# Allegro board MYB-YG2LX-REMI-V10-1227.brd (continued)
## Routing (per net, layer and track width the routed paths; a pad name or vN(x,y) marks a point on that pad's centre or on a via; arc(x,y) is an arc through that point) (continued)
VDD_3V3: length 106.5
  TOP w0.254: U15.3 35.21,21.28 v1(34.97,21.51) 35.19,21.73 U15.2 ; U10.28 98.86,52.06 v1(99.39,51.54) ; U10.21 93.8,53.01 v1(93.58,53.23) ; U7.19 v1(24.19,36.67) ; v1(95.07,57.68) 95.4,57.35 U10.14
  TOP w0.381: v1(13.05,27.3) 13.08,27.3 13.62,27.84 R83.1 ; R85.1 v1(14.17,34.36) ; R11.1 C19.1 v1(32.74,47.37) ; R175.2 96.95,43.21 96.57,43.59 v1(95.88,43.59) ; R175.2 R174.2 ; R175.2 v1(96.3,42.88) ; U24.16 40.21,53.51 40.21,53.51 40.75,53.51 v1(41.19,53.95) ; R138.2 R137.2 v1(98.09,23.8) ; v1(31.01,50.16) 31.01,50.25 R241.2 ; R84.1 v1(14.2,30.5) ; 30.73,32.08 30.73,37.57 30.15,38.15 v1(27.94,38.15) 27.77,37.98 R32.1 ; R33.1 v1(27.89,35.12)
  ART03 w0.381: v1(74.01,13.79) 74.34,13.79 75.26,14.71 v1(75.74,14.71)
  ART04 w0.381: v1(24.19,36.67) 25.67,38.15 v1(27.94,38.15) ; v1(27.89,35.12) 27.89,34.06 v1(29.38,32.56) ; v1(84.15,67.45) 84.15,65 84.79,64.36 v1(84.79,55.26)
  BOTTOM w0.203: C39.1 47.6,19.48 U8.7
  BOTTOM w0.254: v1(22.58,5.38) 22.2,5.01 U14.3 20.36,5.01 20.18,5.19 20.18,6.3 20.51,6.63 C90.1 ; v1(19.4,5.01) U14.6 17.9,5.01 17.5,5.41 R108.1 ; v1(41.77,48.73) 40.62,48.73 40.4,48.96 U23.16
  BOTTOM w0.305: v1(83.21,15.44) 82.75,15.44 R43.1
  BOTTOM w0.381: C33.1 C34.1 25.2,35.65 v1(24.19,36.67) ; R193.2 91.44,38.89 90.55,38.89 89.99,38.33 v1(89.99,38.07) 89.99,37.74 v1(89.73,37.49) ; v1(8.61,21.59) 8.49,21.59 8.11,21.97 Q6.1 ; Q7.1 v1(8.79,28.45) ; R249.1 v1(84.15,67.45) ; C39.1 47.27,17.99 C40.1 v1(46.26,17.64) ; R250.1 v1(105.15,3.87) ; R46.1 R44.1 73.78,13.56 v1(74.01,13.79) ; v1(98.14,11.43) 97.25,11.43 96.66,12.03 R164.1 ; v1(99.39,51.54) 98.84,52.08 C62.1 ; R201.1 v1(99.6,29.91) ; v1(31.01,50.16) 31.01,50.37 31.75,51.11 R241.2 ; R257.1 8.3,26.55 v1(8.51,26.75) ; v1(95.07,57.68) 96.02,56.73 C60.1 ; R267.1 9.91,31.78 v1(9.8,31.67) ; v1(92.2,21.74) 91.81,21.36 R156.2 ; v1(114.98,6.65) 115.23,6.4 R247.1 ; v1(8.66,35) 8.75,35.09 Q9.1 ; v1(96.36,29.95) 96.36,30.82 R199.1 R200.1 ; C63.1 v1(93.58,53.23) ; Q8.1 9.29,32.17 v1(9.29,32.36) ; R115.1 35.71,22.25 v1(34.97,21.51) ; R254.1 v1(41.97,47.52) ; v1(102.97,3) R57.2 ; R261.1 8.18,19.41 v1(8.53,19.76) ; R54.1 v1(93.52,54.13) ; R263.1 v1(9.9,34.83) ; C61.1 v1(100.02,56.54) ; R107.1 v1(22.58,5.38) ; R39.1 v1(84.79,55.26) ; v1(92.76,10.77) 93.37,10.77 93.73,11.14 R162.1 R163.1
  vias: v1(10.46,60.15) v1(10.46,59.74) v1(10.46,59.33) v1(10.87,60.15) v1(10.87,59.74) v1(10.87,59.33) v1(24.68,48.11) v1(24.66,47.62) v1(25.14,48.08) v1(25.09,47.62) v1(25.55,47.68) v1(25.95,47.75) v1(29.38,32.13) v1(29.82,32.56) v1(29.82,32.13) v1(31.8,18.11) v1(31.82,17.68) v1(32.23,18.08) v1(32.25,17.65) v1(39.32,63.47) v1(39.32,63.04) v1(39.32,62.64) v1(39.32,62.2) v1(39.32,61.8) v1(39.39,37.94) v1(39.39,37.51) v1(39.39,37.05) v1(39.72,63.47) v1(39.82,37.94) v1(39.82,37.51) v1(39.82,37.05) v1(40.26,37.94) v1(40.26,37.51) v1(40.26,37.05) v1(47.14,15.52) v1(47.16,15.98) v1(47.6,15.95) v1(47.57,15.49) v1(54.56,15.44) v1(54.96,15.44) v1(59.18,61.9) v1(59.18,61.49) v1(59.58,61.9) v1(59.58,61.49) v1(71.45,62.94) v1(71.45,62.53) v1(71.45,62.13) v1(71.45,61.72) v1(89.38,13.31) v1(89.38,12.9) v1(89.84,13.28) v1(89.84,12.87) v1(99.5,28.53) v1(99.5,27.87) v1(100.63,10.59) v1(101.16,10.62) v1(101.49,24.59) v1(101.6,30.22) v1(102.13,30.22) v1(102.18,24.59)
VDD_5V: length 24.1
  TOP w0.381: R10.1 31.99,44.52 v1(32.3,44.83) ; v1(42.9,27.86) 42.62,28.14 R16.1
  ART03 w0.381: v1(39.52,34.29) 39.52,32.64 40.03,32.13 40.94,32.13 42.9,30.18 v1(42.9,27.86)
  BOTTOM w0.254: v1(79.96,10.36) 80.69,10.36 80.94,10.62 U9.24 ; U14.7 19.3,5.51 19.61,5.82 C91.1
  BOTTOM w0.381: C42.1 76.65,12.09 R38.1 ; D26.1 v1(16.4,14.45) ; R110.1 v1(23.63,7.15) ; v1(17.09,7.24) 16.58,7.24 16.19,6.85 R109.1 ; D25.1 v1(13,13.97) ; C91.1 19.61,7.51 v1(19.1,8.03)
  vias: v1(11.1,41.1) v1(11.1,40.59) v1(11.6,41.1) v1(11.6,40.59) v1(12.11,41.1) v1(12.11,40.59) v1(13.43,18.14) v1(13.43,17.37) v1(14.19,18.14) v1(14.19,17.37) v1(14.96,18.14) v1(14.96,17.37) v1(16.17,60.3) v1(16.17,59.87) v1(16.17,59.41) v1(16.61,60.3) v1(16.61,59.87) v1(16.61,59.41) v1(17.04,60.3) v1(17.04,59.87) v1(17.04,59.41) v1(17.47,60.3) v1(17.47,59.87) v1(17.47,59.41) v1(30.14,39.83) v1(30.14,39.4) v1(30.14,38.94) v1(30.19,10.64) v1(30.19,10.21) v1(30.19,9.78) v1(30.45,16.69) v1(30.45,16.26) v1(30.45,15.8) v1(30.58,39.83) v1(30.58,39.4) v1(30.58,38.94) v1(30.63,10.64) v1(30.63,10.21) v1(30.63,9.78) v1(30.88,16.69) v1(30.88,16.26) v1(30.88,15.8) v1(31.01,39.83) v1(31.01,39.4) v1(31.01,38.94) v1(31.06,10.64) v1(31.06,10.21) v1(31.06,9.78) v1(31.31,16.69) v1(31.31,16.26) v1(31.31,15.8) v1(31.49,10.64) v1(31.49,10.21) v1(31.49,9.78) v1(31.74,16.69) v1(31.74,16.26) v1(31.74,15.8) v1(40.92,66.55) v1(40.92,66.14) v1(41.32,66.55) v1(41.32,66.14) v1(41.73,66.55) v1(41.73,66.14) v1(76.32,9.32) v1(76.32,8.86) v1(76.88,9.32) v1(76.88,8.86) v1(93.95,2.9) v1(94.36,2.9) v1(94.76,2.9) v1(95.17,2.87) v1(95.44,48.41) v1(95.44,47.9) v1(95.94,48.41) v1(95.94,47.9) v1(100.87,47.7) v1(100.87,47.19) v1(100.87,46.69) v1(101.38,47.7) v1(101.38,47.19) v1(101.38,46.69)
VDD_5V_VBUS: length 1.3
  BOTTOM w0.381: v1(94.61,51.54) 95.14,51.54 R55.1
  vias: v1(106.17,50.16) v1(106.17,49.66) v1(106.17,49.15) v1(106.68,50.16) v1(106.68,49.66) v1(106.68,49.15)
VDD_ADC_VREF: length 3.4
  TOP w0.254: v1(41.78,20.85) 41.49,20.85 C107.1 41,21.28 U15.19
  BOTTOM w0.254: v1(41.78,20.85) 41.4,21.23 R130.2
VDD_BAT: length 30.6
  ART04 w0.381: v1(69.82,63.86) v1(70.23,63.86) v1(70.63,63.86) 71.93,63.86 72.44,63.35 78.2,63.35 83.1,68.25 86.66,68.25 88.95,65.96 88.95,60.52 J14.1
VDD_BL_3V3: length 44.8
  TOP w0.254: R236.2 v1(25.23,41.36) ; v1(27.9,41.31) 28.28,41.69 R211.2 ; R235.2 v1(23.45,41.31) ; v1(19.3,41.35) 19.3,41.7 R238.2 ; R239.2 v1(19.9,41.38) ; R237.2 v1(16.34,41.31) ; R240.2 v1(21.68,41.31) ; R215.2 v1(27.01,41.31)
  TOP w0.381: v1(27.81,46.35) 28.16,46 29.94,46 30.43,46.49 v1(31.24,46.49) ; v1(27.81,46.35) v1(27.81,47.32) ; v1(27.81,46.35) 26.08,46.35 25.69,45.96 U22.34 25.69,44.82 v1(26.11,44.4) ; v1(27.81,46.35) 27.49,46.03 U22.36 v1(27.49,44.27)
  TOP w0.508: R214.2 32.06,59.78 31.57,60.27 29.38,60.27 27.02,57.91 27.02,53.34 v1(27.89,52.48)
  ART03 w0.381: v1(16.34,41.31) 16.34,46.01 17.85,47.52 19.47,47.52 19.85,47.14 v1(20.24,47.14)
  BOTTOM w0.381: v1(16.34,41.31) 17.07,42.04 18.92,42.04 19.3,41.66 v1(19.3,41.35) ; R229.1 21.15,47.14 v1(20.24,47.14) ; R213.2 v1(31.24,46.49) ; v1(27.89,52.48) 27.89,52.62 28.27,53 R212.2
VDD_LDO: length 9.8
  TOP w0.102: 68.85,10.53 68.85,11.85 ; 69.85,10.53 69.85,11.85 ; 67.85,10.53 67.85,11.85 ; 70.85,10.53 70.85,11.85
  TOP w0.203: 67.79,10.31 67.41,9.93 v1(67.41,9.46)
  BOTTOM w0.152: v1(67.41,9.46) 67.06,9.12 66.44,9.12 66.23,9.33 U2.7
  BOTTOM w0.381: R3.2 v1(71.07,12.81) 71.13,12.75 C13.1
VDD_PHY0_3V3: length 2.1
  TOP w0.152: 90.32,17.68 90.44,17.56 U16.31
  TOP w0.254: R155.1 v1(100.05,23.8)
  vias: v1(90.52,17.91) v1(90.93,17.91) v1(101.52,21.46) v1(102.51,21.49)
VDD_PHY1_3V3: length 25.9
  TOP w0.152: U19.31 90.41,37.19 90.32,37.29
  TOP w0.254: v1(99.31,43.71) 99.61,43.41 R191.1
  ART04 w0.508: 92.45,37.77 92.45,38.76 93.26,39.57 96.11,39.57 97.25,40.72 98.14,40.72 98.65,41.22 98.65,42.42 99.31,43.08 v1(99.31,43.71) ; 92.45,37.36 92.45,32.34 v1(93.03,31.77) 93.14,31.66 93.59,31.66 v1(96.26,28.98) v1(96.92,28.98)
  BOTTOM w0.254: v1(93.03,31.77) C133.1 C134.1
  vias: v1(90.5,37.54) v1(90.9,37.54)
VDD_RGMII0: length 4.7
  TOP w0.254: v1(90.39,19.1) 91.14,18.36 U16.29
  TOP w0.305: v1(89.85,19.11) 89.86,19.1 v1(90.39,19.1)
  BOTTOM w0.254: R159.1 v1(86.65,28.41) ; R161.1 86.27,26.25 v1(86.65,26.63) R160.1
VDD_RGMII1: length 7
  TOP w0.203: U19.29 90.93,37.99 90.72,38.2 v1(90.72,38.23)
  BOTTOM w0.254: C148.1 R193.1 ; R198.1 84.18,44.51 v1(84.1,44.42)
  BOTTOM w0.305: v1(84.2,49.33) 85.28,50.4 R196.1 ; R197.1 84.18,41.99 v1(84.07,41.88)
  vias: v1(90.62,34.37) v1(90.62,33.81)
VDD_RTC: length 0.8
  BOTTOM w0.381: R256.1 v1(72,69.02)
  vias: v1(67.94,65) v1(67.94,64.59) v1(68.35,65) v1(68.35,64.59) v1(73.91,65.61) v1(73.91,65.2) v1(74.32,65.61) v1(74.32,65.2)
VDD_SD: length 31.8
  BOTTOM w0.381: R70.1 19.38,53.4 19.1,53.68 ; v1(15.44,51.13) 15.44,51.32 15.67,51.56 R72.1 ; 19.1,53.68 18.72,53.3 R71.1 ; 19.1,53.68 v1(19.1,54.13) ; R74.1 8.76,53.32 v1(8.35,52.91) ; R69.1 32.26,55.07 33.07,55.88 33.07,57.03 32.73,57.36 R68.1 31.71,59.22 31.29,59.64 21.32,59.64 v1(19.35,57.66) 19.25,57.56 J5.4 ; R73.1 12.91,51.44 v1(12.57,51.1)
  vias: v1(7.79,60.96) v1(7.79,60.55) v1(7.79,60.15) v1(8.2,60.96) v1(8.2,60.55) v1(8.2,60.15)
VDD_SOM_3V3OUT: length 228.9
  TOP w0.381: U26.87 v1(44.3,50.18)
  ART03 w0.508: v1(90.57,3.23) 90.9,3.56 99.95,3.56 100.19,3.8 v1(103,3.8) ; v1(58.7,8.33) 57.65,8.33 56.36,7.04 36.11,7.04 31.26,11.89 25.55,11.89 24.02,10.36 16.35,10.36 14.27,12.45 8.99,12.45 7.9,13.54 7.9,36.68 9.72,38.51 9.72,56.97 9.42,57.28 9.42,61.04
  ART04 w0.381: v1(44.3,50.18) 45.07,50.95 45.07,55.84 49.12,59.89 49.12,63.83 50.12,64.83 50.12,66.11 48.54,67.69 40.08,67.69 38.86,68.91 16.26,68.91 15.58,68.22 14.14,68.22 12.98,67.06 12.98,64.97 11.96,63.96 11.96,63.02 10.66,61.72 v1(10.64,61.72)
  ART04 w0.508: v1(90.57,3.23) 90.57,5.82 87.42,8.97 84.1,8.97 82.5,7.37 79.78,7.37 77.01,10.13 70.51,10.13 69.9,9.53 69.9,8.84 68.4,7.34 63.34,7.34 61.82,8.86 59.91,8.86 59.38,8.33 v1(58.7,8.33)
  BOTTOM w0.381: C173.1 46.67,50.18 U26.87 v1(44.3,50.18) ; R56.2 102.62,7.44 103,7.06 v1(103,3.8) R253.1
  vias: v1(10.64,61.32) v1(10.64,60.91)
VDD_SOM_5VIN:
  vias: v1(43.73,53.19) v1(43.73,51.19) v1(44.14,53.19) v1(44.14,51.19) v1(44.55,53.19) v1(44.55,51.19) v1(46.25,53.14) v1(46.25,51.21) v1(46.66,53.14) v1(46.66,51.21) v1(47.06,53.14) v1(47.06,51.21)
VDD_USB0_VBUS:
  vias: v1(78.51,4.5) v1(78.51,3.99) v1(78.51,3.48) v1(81.25,3.48) v1(81.76,4.5) v1(81.76,3.99) v1(81.76,3.48) v1(86.84,8.13) v1(86.84,7.62) v1(86.84,7.11) v1(87.35,8.13) v1(87.35,7.62) v1(87.35,7.11)
VDD_VBUS: length 0.2
  TOP w0.254: 63.33,7.15 J1.A4
  vias: v1(58.29,5.94) v1(58.29,5.51) v1(58.29,5.05) v1(58.72,5.94) v1(58.72,5.51) v1(58.72,5.05) v1(59.15,5.94) v1(59.15,5.51) v1(59.15,5.05) v1(59.58,5.94) v1(59.58,5.51) v1(59.58,5.05) v1(63.22,8.76) v1(63.22,8.33) v1(63.65,8.76) v1(63.65,8.33) v1(64.16,6.3) v1(67.71,6.38) v1(68.04,8.76) v1(68.04,8.33) v1(68.27,9.88) v1(68.27,9.45) v1(68.47,8.76) v1(68.47,8.33) v1(68.7,9.88) v1(68.7,9.45)
VDD_VBUS_5V: length 29.9
  ART04 w0.508: 33.65,18.97 33.65,14.5 35.18,12.98 37.94,12.98 44.37,6.55 52.45,6.55 54.81,4.19
  vias: v1(55.21,4.01) v1(55.21,3.56) v1(55.65,4.01) v1(55.65,3.56) v1(56.08,4.01) v1(56.08,3.56) v1(56.51,4.01) v1(56.51,3.56) v1(56.97,3.99) v1(56.97,3.53) v1(57.4,3.99) v1(57.4,3.53)
VDDA_AUDIO_3V3: length 3.7
  TOP w0.254: U15.17 39.84,20.38 39.98,20.24 39.98,19.85 ; U15.16 39.9,19.93 39.98,19.85 ; 39.98,19.85 40.23,19.6 v1(40.23,19.23)
  BOTTOM w0.381: 39.57,18.03 39.57,18.57 v1(40.23,19.23)
VDDA_PHY0_1V1: length 16.9
  TOP w0.203: v1(98.48,16.56) 98.28,16.76 U16.4 ; U16.9 98.56,18.76 v1(98.65,18.85)
  TOP w0.254: U16.47 96.56,14.33 97,13.89 v1(97.02,13.89)
  ART04 w0.508: 98.73,22.48 97.25,21.01 97.25,20.24 v1(98.65,18.85) 98.65,16.76 98.5,16.61 98.5,16.59 v1(98.48,16.56) 98.47,16.56 98.44,16.56 97.02,15.14 v1(97.02,13.89)
  BOTTOM w0.254: U16.9 98.56,18.76 v1(98.65,18.85) ; v1(98.62,24.48) FB11.2 97.5,24.48 ; C127.1 96.88,14.04 v1(97.02,13.89) ; v1(98.48,16.56) 98.28,16.76 U16.4
  vias: v1(99.03,24.49)
VDDA_PHY0_3V3: length 15.4
  TOP w0.254: v1(97.99,20.62) 97.76,20.4 U16.12 ; U16.1 97.76,14.48 98.42,13.82 v1(98.52,13.82)
  ART04 w0.508: v1(101.09,13.54) 101.06,13.51 v1(100.55,13.51) 99.69,14.38 ; v1(97.99,20.62) 98.78,20.62 99.69,19.71 99.69,14.38 ; 99.69,14.38 99.69,14.33 99.18,13.82 v1(98.52,13.82)
  BOTTOM w0.254: U16.12 97.76,20.4 v1(97.99,20.62) ; v1(98.52,13.82) 99.47,13.82 C120.1
VDDA_PHY1_1V1: length 16.8
  TOP w0.203: v1(98.48,36.2) 98.28,36.39 U19.4
  TOP w0.254: U19.47 96.56,33.99 97.55,32.99 v1(97.81,32.99) ; U19.9 98.56,38.39 v1(98.65,38.48)
  ART04 w0.508: v1(97.81,32.99) 97.81,35.54 v1(98.48,36.2) 98.65,36.37 v1(98.65,38.48) 99.49,39.32 v1(99.49,41.33) 99.95,41.33 v1(99.97,41.3)
  BOTTOM w0.254: C143.1 98.03,35.76 v1(98.48,36.2) ; C144.1 97.76,37.97 98.27,38.48 v1(98.65,38.48) ; v1(97.81,32.99) 97.4,32.99 96.88,33.52 C145.1
VDDA_PHY1_3V3: length 21.6
  TOP w0.254: v1(97.79,40.06) 97.76,40.03 U19.12 ; v1(98.62,33.73) 97.76,34.6 U19.1
  ART04 w0.508: v1(97.79,40.06) 97.79,37.06 96.74,36.02 96.74,32.59 97.46,31.88 100.45,31.88 101.09,32.51 v1(101.09,33.12) ; v1(101.09,33.12) 100.07,34.14 99.03,34.14 v1(98.62,33.73) ; v1(101.09,33.12) v1(101.62,33.12)
  BOTTOM w0.254: C135.1 97.76,40.03 v1(97.79,40.06) ; v1(98.62,33.73) 97.8,34.56 C136.1
VDDL_PHY0_1V1: length 38
  TOP w0.254: v1(92.73,24.63) 92.73,23.37 93.11,22.99 C124.1 U16.22
  ART04 w0.381: 88.41,14.71 88.41,18.26 87.96,18.72 85.67,18.72 84.2,20.19 84.2,29.08 85.06,29.95 86.71,29.95 87.17,29.49 91.21,29.49 92.17,28.52 92.17,27.1 92.71,26.57 93.67,26.57 ; 88.41,14.71 v1(87.63,14.71) ; 88.41,14.71 88.41,13.13 87.96,12.67 v1(87.63,12.67)
  BOTTOM w0.254: 96.2,24.48 v1(96.2,25.32)
  vias: v1(96.21,25.73)
VDDL_PHY1_1V1: length 1
  TOP w0.254: U19.22 v1(93.36,41.35)
  vias: v1(84.78,40.89) v1(85.21,41.35) v1(85.21,40.89) v1(100.1,44.22) v1(100.55,44.22)
32.7K_CLK: length 4.4
  TOP w0.152: U22.31 v1(22.99,46.17)
  BOTTOM w0.152: R232.2 23.94,47.9 C158.1 R233.1 24.05,46.74 23.49,46.17 v1(22.99,46.17)
AUD_MIC: length 32.8
  TOP w0.203: J8.5 44.61,2.2 44.92,2.51 D29.2 44.92,4.14 C105.1 R131.1 39.8,10.15 39.8,11.61 40.31,12.12 42.06,12.12 43.56,13.61 43.56,18.39 43.68,18.52 43.68,19.13 43.25,19.56 v1(41.93,19.56)
  BOTTOM w0.203: v1(41.93,19.56) 40.52,20.97 R130.1 40.52,24.32 R129.1
AUDIO1_LOUT_L: length 10.1
  TOP w0.381: J8.3 34.14,9.2 35.89,10.95 v1(35.89,12.37) ; v1(37.61,12.37) 37.63,12.38 D27.2 R124.1 39.35,13.04 C97.1 39.55,13.03 40.25,13.74 R116.2
  BOTTOM w0.381: v1(35.89,12.37) v1(37.61,12.37)
AUDIO1_LOUT_R: length 14.1
  TOP w0.381: R123.2 35.61,13.03 C98.1 35.9,13.04 D28.2 36.74,10.83 36.01,10.11 36.01,7.26 37.78,5.5 J8.6
AUDIO_AGND: length 41.5
  TOP w0.254: C108.2 42.5,22.61 v1(43.28,22.61) ; v1(43.23,21.31) C107.2 42.48,20.77 42.08,20.37 40.94,20.37 40.48,20.83 U15.18 ; R127.2 v1(42.96,17.98)
  TOP w0.381: D27.1 v1(37.63,14.61) ; D28.1 v1(36.74,14.61) ; C97.2 v1(39.36,14.6) ; C98.2 v1(35.89,14.6) ; R124.2 v1(38.52,14.61)
  TOP w0.508: J8.2 34.28,2.2 36.22,4.14 41.42,4.14 42.26,3.31 D29.1 44.04,4.14 C105.2 R131.2 39.19,9.88 39.19,11.73 v1(40.19,12.74) v1(40.95,12.74) v1(41.72,12.74)
  BOTTOM w0.152: 41.55,14.38 41.78,14.38
  BOTTOM w0.508: C106.2 38.71,19.35 39.19,19.84 40.61,19.84 41.68,18.77 42.59,18.77
AUDIO_MCLK: length 3.2
  TOP w0.152: U15.1 35.68,24.38 C94.1 R114.2
CARRIER_PWR_ON: length 42
  TOP w0.152: v1(35.81,26.09) 35.86,26.09 36.32,26.54 37.05,26.54 37.39,26.21 R8.1 ; R15.1 30.22,41.68 30.42,41.48 v1(30.93,41.48) ; v1(43.68,44.55) 43.68,47.93 43.93,48.18 U26.89
  ART04 w0.152: v1(30.93,41.48) 30.93,40.77 31.87,39.83 31.87,37.87 31.35,37.35 31.35,28.77 34.03,26.09 v1(35.81,26.09)
  BOTTOM w0.152: v1(30.93,41.48) 31.44,40.97 33.75,40.97 37.33,44.55 v1(43.68,44.55)
CC1: length 5.7
  TOP w0.254: J1.A5 64.63,9.05 v1(64.51,9.17) 63.94,9.17 63.65,9.46 63.65,10.19 v1(63.57,10.26)
  BOTTOM w0.152: R5.2 63.5,10.34 v1(63.57,10.26) 63.65,10.34 64.37,10.34 U2.11
  BOTTOM w0.254: D3.2 v1(64.51,9.17)
CC2: length 7.4
  TOP w0.254: J1.B5 67.63,8.03 v1(67,8.66) 66.95,8.66 65.86,9.75 v1(64.49,9.75)
  BOTTOM w0.152: U2.10 64.57,9.68 v1(64.49,9.75) 64.41,9.75 64.11,9.45 R6.2
  BOTTOM w0.254: v1(67,8.66) 67.03,8.64 D2.2
CSI_CLK_N: length 2.4
  TOP w0.13: U6.A2 12.87,52.54 12.54,52.54 12.22,52.22 12.22,51.92 12.14,51.83 11.84,51.83 11.76,51.92 J2.18
CSI_CLK_P: length 2.4
  TOP w0.13: J2.17 11.77,51.42 11.85,51.5 12.27,51.5 12.55,51.78 12.55,52.08 12.68,52.21 12.87,52.21 U6.A1
CSI_DATA0_N: length 2.2
  TOP w0.13: U6.A6 12.9,54.18 12.57,54.18 11.92,54.83 11.1,54.83 J2.24
CSI_DATA0_P: length 2.2
  TOP w0.13: U6.A5 12.84,53.85 12.44,53.85 11.78,54.5 11.1,54.5 J2.23
CSI_DATA1_N: length 1.9
  TOP w0.13: J2.21 11.62,53.42 11.7,53.33 12.52,53.33 12.57,53.38 U6.A4
CSI_DATA1_P: length 1.9
  TOP w0.13: J2.20 11.62,52.92 11.7,53 12.54,53 12.57,52.98 U6.A3
CSI_DATA2_N: length 2
  TOP w0.13: J2.15 11.62,50.42 11.7,50.33 11.89,50.33 11.96,50.4 12.5,50.4 12.54,50.44 U5.A4
CSI_DATA2_P: length 2
  TOP w0.13: J2.14 11.62,49.92 11.7,50 12.02,50 12.09,50.07 12.5,50.07 12.54,50.04 U5.A3
CSI_DATA3_N: length 2.4
  TOP w0.13: U5.A2 12.87,49.6 12.54,49.6 12.22,49.28 12.22,48.97 12.08,48.83 11.69,48.83 11.61,48.92 J2.12
CSI_DATA3_P: length 2.4
  TOP w0.13: J2.11 11.58,48.42 11.67,48.5 12.22,48.5 12.55,48.84 12.55,49.14 12.68,49.27 12.87,49.27 U5.A1
ET0_LED1: length 11.6
  TOP w0.254: U16.36 91.76,14.43 v1(92.2,14)
  BOTTOM w0.254: v1(92.2,14) 93.95,14 R163.2 R165.1 95.56,13.33 96.08,12.8 96.08,11.66 96.85,10.9 98.9,10.9 99.16,10.64 99.16,10.19 R151.2
ET0_LED2: length 9.9
  TOP w0.254: v1(94.69,14) 92.91,14 92.56,14.35 U16.37
  BOTTOM w0.254: v1(94.69,14) 95.94,14 96.61,13.33 R164.2 R166.1 98.57,13.33 98.88,13.02 98.88,12.36 99.13,12.11 R152.2
ET0_LINKSTA: length 55.8
  TOP w0.152: U26.L1 v1(85.37,14.63)
  ART03 w0.152: v1(85.37,14.63) 77.44,14.63 75.21,12.4 68.82,12.4 67.31,13.92 61.44,13.92 60.96,13.44 49.78,13.44 48.15,15.06 48.15,16.7 47.05,17.8 47.05,20.04 44.32,22.77 43.69,22.77 43.45,23.01 40.26,23.01 v1(39.87,22.63)
  BOTTOM w0.152: v1(39.87,22.63) 39.5,22.25 R117.1
ET0_MDC: length 22.5
  TOP w0.152: v1(97.46,25.37) T14.1 98.1,24.42 98.6,23.93 98.6,22.5 98.44,22.34 R137.1 97.26,21.51 96.97,21.51 96.56,21.1 U16.14 ; v1(87.37,33.78) 87.77,34.18 U26.22
  BOTTOM w0.152: v1(87.37,33.78) 87.77,34.18 88.42,34.18 92.68,29.92 94.32,29.92 97.46,26.78 v1(97.46,25.37)
ET0_MDIO: length 26.5
  TOP w0.152: R138.1 v1(96.74,21.88) 96.16,21.3 U16.15 ; v1(86.76,33.78) 88.16,35.18 U26.23
  BOTTOM w0.152: v1(86.76,33.78) 87.57,34.59 88.59,34.59 92.93,30.25 94.42,30.25 99.64,25.03 99.64,23.39 99.41,23.16 98.02,23.16 v1(96.74,21.88)
ET0_PHYAD0: length 5.3
  TOP w0.254: v1(91.51,14) 91.41,14 91.06,14.35 91.06,15.7 91.32,15.96 U16.35
  BOTTOM w0.254: R162.2 R173.1 92.18,13.33 v1(91.51,14)
ET0_RX_CTL: length 4.6
  TOP w0.152: U26.16 89.42,28.18 v1(90.09,27.51)
  BOTTOM w0.152: R160.2 R171.1 R146.2 v1(90.09,27.51)
ET0_RXC: length 5.6
  TOP w0.152: U26.15 85.9,27.18 v1(85.82,27.1)
  BOTTOM w0.152: v1(85.82,27.1) 85.39,26.67 R161.2 R172.1 R145.2
ET0_RXD0: length 4.4
  TOP w0.152: U26.17 v1(86.64,29.18)
  BOTTOM w0.152: v1(86.64,29.18) 86.75,29.29 R159.2 R170.1 R147.2
ET0_RXD1: length 2.4
  TOP w0.152: v1(87.45,30.15) 87.48,30.18 U26.18
  BOTTOM w0.152: R169.1 87.42,30.18 v1(87.45,30.15) 87.48,30.18 R148.2
ET0_RXD2: length 2.5
  TOP w0.152: v1(87.45,31.22) 87.48,31.18 U26.19
  BOTTOM w0.152: R168.1 87.41,31.18 v1(87.45,31.22) 87.48,31.18 R149.2
ET0_RXD3: length 2.4
  TOP w0.152: U26.20 v1(87.45,32.18)
  BOTTOM w0.152: R167.1 v1(87.45,32.18) R150.2
ET0_TRN0: length 14.4
  TOP w0.13: U16.3 98.12,16.36 98.31,16.17 98.36,16.17 98.8,15.73 98.8,15.27 99.24,14.83 99.54,14.83 99.69,14.98 U17.6 99.91,14.83 100.73,14.83 101.34,15.44 103.22,15.44 103.88,14.78 103.88,13.03 104.31,12.6 108.51,12.6 J9.2
ET0_TRN1: length 12.9
  TOP w0.13: U16.6 97.8,17.52 98.54,17.52 99.3,16.76 99.65,16.76 U17.4 99.88,16.76 100.65,16.76 101.23,17.35 103.32,17.35 105.52,15.15 106.95,15.15 107.43,14.68 107.5,14.54 107.65,14.48 J9.4
ET0_TRN2: length 12.2
  TOP w0.13: J9.8 107.65,19.56 107.47,19.62 106.87,20.23 104.57,20.23 103.37,19.02 101.34,19.02 100.76,18.44 99.9,18.44 U18.6 99.62,18.44 98.8,18.44 98.68,18.32 98.46,18.32 98.42,18.36 U16.8
ET0_TRN3: length 13
  TOP w0.13: J9.10 107.73,22.14 107.54,22.17 106.6,23.11 105.17,23.11 102.99,20.93 101.34,20.93 100.75,20.35 99.89,20.35 U18.4 99.63,20.35 99.05,20.35 98.23,19.52 97.8,19.52 U16.11
ET0_TRP0: length 14.4
  TOP w0.13: U16.2 98.06,15.96 98.18,15.84 98.23,15.84 98.47,15.59 98.47,15.14 99.11,14.5 100.87,14.5 101.48,15.12 102.02,15.12 U17.1 102.27,15.09 103.11,15.09 103.55,14.65 103.55,12.89 104.18,12.27 104.49,12.27 104.61,12.16 104.61,11.42 104.72,11.3 104.88,11.3 105,11.42 105,12.14 105.13,12.27 105.94,12.27 106.12,12.09 J9.1
ET0_TRP1: length 12.9
  TOP w0.13: U16.5 97.8,17.19 98.4,17.19 99.16,16.43 100.78,16.43 101.37,17.02 102.02,17.02 U17.3 102.3,17.02 103.19,17.02 105.38,14.82 106.82,14.82 107.16,14.48 107.28,14.25 107.17,13.92 106.5,13.59 J9.3
ET0_TRP2: length 12.2
  TOP w0.13: J9.7 107.06,18.8 107.26,19 107.26,19.37 106.73,19.9 104.71,19.9 103.48,18.67 102.26,18.67 U18.1 102.04,18.7 101.48,18.7 100.89,18.11 98.94,18.11 98.82,17.99 98.46,17.99 98.42,17.96 U16.7
ET0_TRP3: length 13
  TOP w0.13: J9.9 106.91,21.34 107.26,21.69 107.26,21.99 106.46,22.79 105.31,22.79 103.12,20.6 102.29,20.6 U18.3 102.12,20.48 101.99,20.6 101.47,20.6 100.89,20.02 99.19,20.02 98.36,19.2 97.8,19.2 U16.10
ET0_TX_CTL: length 2
  TOP w0.152: U26.12 v1(87.36,24.18)
  BOTTOM w0.152: U26.12 v1(87.36,24.18)
ET0_TXC: length 2
  TOP w0.152: U26.11 v1(87.36,23.18)
  BOTTOM w0.152: U26.11 v1(87.36,23.18)
ET0_TXD0: length 2.2
  TOP w0.152: v1(87.4,24.82) 87.76,25.18 U26.13
  BOTTOM w0.152: U26.13 87.76,25.18 v1(87.4,24.82)
ET0_TXD1: length 2
  TOP w0.152: U26.10 v1(87.36,22.18)
  BOTTOM w0.152: U26.10 v1(87.36,22.18)
ET0_TXD2: length 2
  TOP w0.152: U26.8 v1(87.36,20.18)
  BOTTOM w0.152: U26.8 v1(87.36,20.18)
ET0_TXD3: length 2
  TOP w0.152: U26.9 v1(87.36,21.18)
  BOTTOM w0.152: U26.9 v1(87.36,21.18)
ET1_LED1: length 15.8
  TOP w0.254: U19.36 91.76,34.14 92.83,33.07 v1(94.43,33.07)
  BOTTOM w0.254: v1(94.43,33.07) 95.02,33.07 95.8,32.28 96.8,32.28 R200.2 R202.1 98.56,31.77 98.83,31.5 98.83,29.97 100.15,28.65 100.15,27.05 100.66,26.54 101.54,26.54 R188.2
ET1_LED2: length 12.6
  TOP w0.254: v1(93.87,33.6) 92.91,33.6 92.56,33.95 U19.37
  BOTTOM w0.254: R189.2 101.09,29.49 101.09,31.5 101.08,31.5 100.81,31.77 R203.1 R201.2 99.5,31.77 98.95,32.31 97.46,32.31 97.02,32.74 95.98,32.74 95.12,33.6 v1(93.87,33.6)
ET1_MDC: length 26.7
  TOP w0.152: v1(86.65,37.59) 86.65,36.89 87.36,36.18 88.35,36.18 U26.24 ; R174.1 97.78,42 97.1,41.33 v1(97.02,41.33) 96.56,40.86 U19.14 ; T16.1 97.19,44.03 v1(96.67,44.55)
  BOTTOM w0.152: v1(97.02,41.33) 97.15,41.45 97.15,44.17 96.77,44.55 v1(96.67,44.55) 95.88,45.34 91.92,45.34 90.65,44.07 87.4,44.07 86.76,43.43 86.76,42.77 86.53,42.55 86.53,39.6 86.76,39.37 86.76,37.7 v1(86.65,37.59)
ET1_MDIO: length 22.5
  TOP w0.152: U26.25 87.77,37.18 v1(87.36,37.59) ; U19.15 96.16,41.22 v1(96.37,41.42) R175.1
  BOTTOM w0.152: v1(87.36,37.59) 87.07,37.89 87.07,39.65 86.89,39.83 86.89,42.39 87.07,42.57 87.07,43.21 87.6,43.74 90.83,43.74 92.07,44.98 95.66,44.98 96.72,43.93 96.72,41.77 v1(96.37,41.42)
ET1_PHYAD0: length 8.3
  TOP w0.254: v1(93.8,32.61) 92.71,32.61 91.33,33.99 91.33,34.67 91.08,34.92 91.08,35.34 91.33,35.59 U19.35
  BOTTOM w0.254: R199.2 R210.1 94.69,32.61 v1(93.8,32.61)
ET1_RX_CTL: length 5
  TOP w0.152: U26.33 86.76,45.18 v1(86.36,44.78)
  BOTTOM w0.152: v1(86.36,44.78) 86.09,44.51 86.09,44.13 R183.2 R208.1 84.51,44 R197.2
ET1_RXC: length 4.2
  TOP w0.152: U26.34 v1(86.53,46.18)
  BOTTOM w0.152: v1(86.53,46.18) 86.43,46.29 R182.2 R209.1 R198.2
ET1_RXD0: length 4.4
  TOP w0.152: v1(89.56,51.26) 88.48,50.18 U26.38
  BOTTOM w0.152: v1(89.56,51.26) 88.6,51.26 R184.2 R207.1 R196.2
ET1_RXD1: length 2.7
  TOP w0.152: U26.37 v1(87.45,49.18)
  BOTTOM w0.152: R206.1 v1(87.45,49.18) U26.37
ET1_RXD2: length 2.7
  TOP w0.152: U26.36 v1(87.45,48.18)
  BOTTOM w0.152: U26.36 v1(87.45,48.18) R205.1
ET1_RXD3: length 2.7
  TOP w0.152: U26.35 v1(87.45,47.18)
  BOTTOM w0.152: U26.35 v1(87.45,47.18) R204.1
ET1_TRN0: length 14.4
  TOP w0.13: U19.3 98.12,35.99 98.31,35.8 98.36,35.8 98.8,35.36 98.8,34.91 99.24,34.47 99.54,34.47 99.69,34.61 U20.6 99.91,34.47 100.73,34.47 101.34,35.08 103.22,35.08 103.88,34.42 103.88,32.67 104.31,32.23 108.51,32.23 J10.2
ET1_TRN1: length 12.9
  TOP w0.13: U19.6 97.8,37.16 98.54,37.16 99.3,36.4 99.65,36.4 U20.4 99.88,36.4 100.65,36.4 101.23,36.98 103.32,36.98 105.52,34.79 106.95,34.79 107.43,34.31 107.5,34.17 107.65,34.12 J10.4
ET1_TRN2: length 12.2
  TOP w0.13: J10.8 107.65,39.2 107.47,39.26 106.87,39.87 104.57,39.87 103.37,38.66 101.34,38.66 100.76,38.08 99.9,38.08 U21.6 99.62,38.07 98.8,38.07 98.68,37.96 98.46,37.96 98.42,37.99 U19.8
ET1_TRN3: length 13
  TOP w0.13: U19.11 97.8,39.16 98.23,39.16 99.05,39.98 99.63,39.98 U21.4 99.89,39.98 100.75,39.98 101.34,40.56 102.99,40.56 105.17,42.75 106.6,42.75 107.54,41.8 107.73,41.78 J10.10
ET1_TRP0: length 14.4
  TOP w0.13: U19.2 98.06,35.59 98.18,35.48 98.23,35.48 98.47,35.23 98.47,34.77 99.11,34.14 100.87,34.14 101.48,34.75 102.02,34.75 U20.1 102.27,34.73 103.11,34.73 103.55,34.28 103.55,32.53 104.18,31.91 104.49,31.91 104.61,31.79 104.61,31.05 104.72,30.94 104.88,30.94 105,31.05 105,31.77 105.13,31.91 105.94,31.91 106.12,31.72 J10.1
ET1_TRP1: length 12.9
  TOP w0.13: U19.5 97.8,36.83 98.4,36.83 99.16,36.07 100.78,36.07 101.37,36.66 102.02,36.66 U20.3 102.3,36.65 103.19,36.65 105.38,34.46 106.82,34.46 107.16,34.12 107.28,33.88 107.17,33.56 106.5,33.23 J10.3
ET1_TRP2: length 12.2
  TOP w0.13: U19.7 98.42,37.59 98.46,37.63 98.82,37.63 98.94,37.75 100.89,37.75 101.48,38.33 102.04,38.33 U21.1 102.26,38.31 103.48,38.31 104.71,39.54 106.73,39.54 107.26,39.01 107.26,38.64 107.06,38.43 J10.7
ET1_TRP3: length 13
  TOP w0.13: J10.9 106.91,40.97 107.26,41.33 107.26,41.63 106.46,42.42 105.31,42.42 103.12,40.24 102.29,40.24 U21.3 102.12,40.11 101.99,40.24 101.47,40.24 100.89,39.65 99.19,39.65 98.36,38.83 97.8,38.83 U19.10
ET1_TX_CTL: length 2
  TOP w0.152: U26.26 87.85,38.18 v1(87.5,38.53)
  BOTTOM w0.152: U26.26 87.85,38.18 v1(87.5,38.53)
ET1_TXC: length 1.9
  TOP w0.152: v1(87.47,42.98) 87.68,43.18 U26.31
  BOTTOM w0.152: U26.31 87.68,43.18 v1(87.47,42.98)
ET1_TXD0: length 1.8
  TOP w0.152: U26.30 v1(87.44,42.18)
  BOTTOM w0.152: U26.30 v1(87.44,42.18)
ET1_TXD1: length 1.8
  TOP w0.152: U26.29 v1(87.44,41.18)
  BOTTOM w0.152: U26.29 v1(87.44,41.18)
ET1_TXD2: length 1.8
  TOP w0.152: U26.28 v1(87.47,40.18)
  BOTTOM w0.152: U26.28 v1(87.47,40.18)
ET1_TXD3: length 1.8
  TOP w0.152: U26.27 v1(87.47,39.18)
  BOTTOM w0.152: U26.27 v1(87.47,39.18)
HOST1_USB_DM: length 3.8
  TOP w0.155: L5.2 102.43,54.57 100.62,54.57 100.14,54.09 99.43,54.09 U10.3
HOST1_USB_DP: length 3.8
  TOP w0.155: L5.3 102.43,54.9 100.48,54.9 100.01,54.42 99.43,54.42 U10.4
HOST2_USB_DM: length 5.6
  TOP w0.155: U10.6 99.94,55.51 100.02,55.59 100.58,55.59 101.04,56.05 101.04,57.75 101.4,58.12 102.42,58.12 L4.2
HOST2_USB_DP: length 5.6
  TOP w0.155: U10.7 99.94,56.01 100.02,55.92 100.44,55.92 100.71,56.19 100.71,57.89 101.27,58.45 102.37,58.45 L4.3
HPD_DET: length 5.7
  TOP w0.254: J7.19 v1(15.63,8.47)
  BOTTOM w0.381: v1(15.63,8.47) 16.58,9.42 R103.1 R106.1
HPGND: length 3.7
  TOP w0.254: U15.13 38.48,18.59 38.73,18.34 39.52,18.34 39.95,18.77 R127.1
INT: length 2.8
  TOP w0.152: U11.63 23.98,20.64 24.41,20.22 25,20.22 R80.2
LT8912_VCCA_HDMIPLL: length 8.6
  TOP w0.203: U11.52 19.58,21.66 19.42,21.82 18.97,21.82 18.78,21.63 U11.50 18.78,20.72 18.13,20.07 v1(18.13,19.99) ; U11.34 17.16,27.52 16.68,28 C72.2
  TOP w0.381: v1(18.13,19.99) 17.88,20.24 17.09,20.24 16.43,20.9 v1(16.43,21.18) ; v1(15.62,27.3) 15.61,27.31 v1(15.61,28) C72.2
  BOTTOM w0.152: 15.61,27.31 v1(15.62,27.3)
LT8912_VCCA_HDMITX: length 34.1
  TOP w0.152: v1(25.9,23.6) 25.82,23.52 U11.5 ; U11.57 v1(21.58,19.94) ; v1(20.75,29.72) 20.78,29.68 U11.26
  TOP w0.203: U11.41 16.94,24.72 v1(16.76,24.54) ; U11.33 17.63,28.46 v1(17.42,28.68) ; v1(24.25,29.57) 23.98,29.3 U11.18
  TOP w0.381: v1(25.9,23.6) v1(26.77,23.6)
  BOTTOM w0.381: v1(24.25,29.57) 24.14,29.45 C78.1 ; C76.1 16.81,24.59 v1(16.76,24.54) ; v1(21.58,19.94) U11.57 ; C74.1 20.58,29.55 v1(20.75,29.72)
  BOTTOM w0.508: v1(17.42,28.68) 17.23,28.87 C73.1 ; v1(17.42,28.68) 18.05,28.05 C87.1 18.05,27.57 17.53,27.06 C76.1 ; v1(17.42,28.68) 17.71,28.97 C74.1 20.58,28.46 21.1,27.94 23.69,27.94 24.14,28.39 C78.1 25.73,28.92 FB3.1 25.93,27.42 25.69,27.18 C79.1 C86.1 ; U11.57 21.7,21.17 22.2,20.68 23.59,20.68 24.34,21.43 C77.1
LVDS_CLK+: length 7.2
  TOP w0.13: U11.39 16.97,25.52 16.94,25.48 14.35,25.48 13.4,24.54 11.83,24.54 11.75,24.62 J6.18
LVDS_CLK-: length 7.2
  TOP w0.13: U11.40 16.97,25.12 16.94,25.15 14.48,25.15 13.54,24.21 11.83,24.21 11.75,24.12 J6.17
LVDS_D0+: length 7.7
  TOP w0.13: J6.9 11.75,20.12 11.83,20.04 13.94,20.04 16.18,22.28 16.94,22.28 16.97,22.32 U11.47
LVDS_D0-: length 7.7
  TOP w0.13: U11.48 16.97,21.92 16.94,21.95 16.32,21.95 14.07,19.71 11.83,19.71 11.75,19.62 J6.8
LVDS_D1+: length 7.4
  TOP w0.13: J6.12 11.75,21.62 11.83,21.54 13.73,21.54 15.27,23.08 16.94,23.08 16.97,23.12 U11.45
LVDS_D1-: length 7.4
  TOP w0.13: J6.11 11.75,21.12 11.83,21.21 13.87,21.21 15.41,22.75 16.94,22.75 16.97,22.72 U11.46
LVDS_D2+: length 7.1
  TOP w0.13: U11.43 16.97,23.92 16.94,23.88 14.22,23.88 13.38,23.04 11.83,23.04 11.75,23.12 J6.15
LVDS_D2-: length 7.1
  TOP w0.13: J6.14 11.75,22.62 11.83,22.71 13.51,22.71 14.36,23.55 16.94,23.55 16.97,23.52 U11.44
LVDS_D3+: length 6.9
  TOP w0.13: U11.37 16.97,26.32 16.94,26.28 13.42,26.28 13.18,26.04 11.83,26.04 11.75,26.12 J6.21
LVDS_D3-: length 6.9
  TOP w0.13: U11.38 16.97,25.92 16.94,25.95 13.55,25.95 13.31,25.71 11.83,25.71 11.75,25.62 J6.20
OVCUR#: length 7
  TOP w0.254: T22.1 93.01,50.85 94.92,50.85 95.47,51.41 v1(96.64,51.41) ; v1(96.64,51.41) 96.9,51.66 U10.25 ; v1(96.64,51.41) 96.4,51.66 U10.24
  BOTTOM w0.381: R55.2 96.57,51.49 v1(96.64,51.41)
POWER_ONOFF: length 15
  TOP w0.152: v1(43.46,54.99) 43.51,54.94 46.91,54.94 48.03,53.82 48.03,51.54 47.16,50.67 47.16,47.47 46.87,47.18 U26.90
  BOTTOM w0.152: R248.1 42.95,54.94 43.4,54.94 v1(43.46,54.99)
PWREN#: length 3.8
  TOP w0.152: U10.8 99.83,56.96 100.11,57.24 R270.2
RESET#: length 2
  TOP w0.152: U10.17 v1(93.45,55.01)
  BOTTOM w0.152: U10.17 v1(93.45,55.01)
RESET_IN_N: length 117.3
  TOP w0.152: U26.88 44.02,49.18 42.9,48.06 41.78,48.06 41.5,47.78 41.5,46.23 42.87,44.86 42.87,42.19 v1(42.64,41.96)
  ART03 w0.152: v1(103.98,7.54) 103.63,7.19 99.64,7.19 98.52,6.07 97.42,6.07 96.3,7.19 90.8,7.19 88.01,9.98 85.77,9.98 84.66,11.09 78.12,11.09 77.72,10.69 67.92,10.69 66.92,11.68 56.89,11.68 56.41,11.2 49.41,11.2 45.06,15.56 45.06,18.33 44.23,19.15 41.49,19.15 37.74,22.9 37.74,28.02 37.31,28.45 37.31,38.23 41.04,41.96 v1(42.64,41.96)
  BOTTOM w0.152: v1(103.98,7.54) 104.19,7.75 109.31,7.75 D36.1
RIIC0_SCL_1V8: length 42.2
  TOP w0.152: R25.1 v1(14.47,46.02) ; v1(14.35,37.26) 14.35,36.5 15.1,35.75 T4.1 16.73,36 R28.2 17.64,36.02 U7.3 22.09,36.02 23.01,35.1 23.01,32.82 v1(24.23,31.6) ; v1(24.99,17.86) 24.89,17.96 R79.1
  ART03 w0.152: v1(24.23,31.6) 25.22,30.61 25.22,28.55 24.25,27.58 24.25,18.59 v1(24.99,17.86) ; v1(14.47,46.02) 12.52,44.07 12.52,40.36 11.86,39.7 11.86,38.68 12.87,37.67 14.04,37.67 14.35,37.36 v1(14.35,37.26)
RIIC0_SDA_1V8: length 43.7
  TOP w0.152: R78.1 24,17.96 v1(25.02,16.94) ; R24.1 v1(14.47,45.13) ; v1(24.18,32.23) 23.36,33.05 23.36,35.64 21.68,37.32 U7.1 18.04,37.32 R27.2 16.5,36.9 T2.1 16.39,36.83 15.06,36.83 v1(14.87,37.02)
  ART03 w0.152: v1(25.02,16.94) 25.45,17.37 25.45,18.16 24.63,18.97 24.63,27.2 25.6,28.17 25.6,30.81 v1(24.18,32.23) ; v1(14.87,37.02) 14.93,37.08 14.93,37.29 14.22,38 13.13,38 12.37,38.76 12.37,39.73 12.82,40.18 12.82,43.48 v1(14.47,45.13)
RIIC1_SCL_5V: length 8.3
  TOP w0.254: v1(17.63,8.26) J7.15 17.63,12.63 R102.2
  BOTTOM w0.254: v1(17.63,8.26) 17.63,7.06 R109.2 17.62,6.5 18.12,6.01 U14.8
RIIC1_SDA_5V: length 14.1
  TOP w0.152: v1(22.75,7.13) 21.99,6.38 18.13,6.38 17.66,6.85 17.66,7.54 17.13,8.08 J7.16 17.13,12.62 R101.2
  BOTTOM w0.152: R110.2 v1(22.75,7.13)
  BOTTOM w0.254: U14.1 21.96,6.01 22.22,6.27 R110.2
RTC_CLK: length 2.6
  BOTTOM w0.152: T19.1 73.31,62.88 U25.3
RZ_AUDIO_CLK_11_2896M: length 8.5
  TOP w0.152: U26.139 61.35,12.03 60.94,12.44 55.36,12.44 v1(54.91,11.99)
  BOTTOM w0.152: v1(54.91,11.99) 54.69,11.99 R134.2
RZ_AUDIO_CLK_12_2880M: length 2.4
  TOP w0.152: v1(62.35,12.57) 62.35,12.04 62.35,12.04 U26.140
  BOTTOM w0.152: v1(62.35,12.57) 62.35,12.63 R136.2
RZ_CAN1_RX: length 53.4
  TOP w0.152: U26.116 v1(44.34,21.18) ; J13.16 v1(57.88,65.02)
  ART04 w0.152: v1(57.88,65.02) 48.41,55.55 48.41,50.57 47.95,50.11 47.39,50.11 46.78,49.5 46.78,46.3 47.62,45.47 47.62,39.88 46.96,39.22 46.96,28.98 45.69,27.71 45.69,22.53 v1(44.34,21.18)
RZ_CAN1_TX: length 56.5
  TOP w0.152: J13.18 v1(60.42,65.02) ; U26.117 v1(44.34,20.18)
  ART04 w0.152: v1(44.34,20.18) 46.91,22.75 46.91,28.07 47.32,28.47 47.32,39.01 48.08,39.78 48.08,45.57 47.27,46.38 47.27,49.4 47.6,49.73 48.43,49.73 48.71,50.01 48.71,54.85 58.87,65.02 v1(60.42,65.02)
RZ_CSI_CLK_N: length 72.1
  TOP w0.13: U6.C2 13.73,52.55 14.08,52.55 14.35,52.28 14.8,52.28 v1(15.03,52.52) ; v1(75.52,53.89) 75.69,54.06 75.69,55.09 75.35,55.43 U26.54
  ART03 w0.109: v1(15.03,52.52) 15.2,52.35 15.49,52.35 15.61,52.48 15.81,52.48 15.94,52.35 16.14,52.35 16.27,52.48 16.47,52.48 16.6,52.35 16.8,52.35 16.92,52.48 17.13,52.48 17.25,52.35 17.45,52.35 17.58,52.48 17.78,52.48 17.91,52.35 19.37,52.35 19.98,52.96 22.47,52.96 25.03,55.52 27.43,55.52 31.01,59.11 40.45,59.11 41.04,59.69 44.78,59.69 45.26,59.21 59.81,59.21 63.24,55.78 66.45,55.78 66.78,55.45 73.96,55.45 74.62,54.79 74.62,53.73 75.03,53.31 75.51,53.31 75.71,53.52 75.71,53.7 v1(75.52,53.89)
RZ_CSI_CLK_P: length 72.1
  TOP w0.13: U26.53 76.35,55.43 76.01,55.09 76.01,54.06 v1(76.18,53.89) ; v1(15.03,51.86) 14.93,51.95 14.21,51.95 13.94,52.22 13.75,52.22 U6.C1
  ART03 w0.109: v1(15.03,51.86) 15.2,52.02 19.51,52.02 20.12,52.63 22.6,52.63 25.17,55.19 27.56,55.19 31.15,58.78 40.59,58.78 41.17,59.36 44.64,59.36 45.12,58.88 59.68,58.88 63.11,55.45 66.32,55.45 66.65,55.12 73.83,55.12 74.29,54.65 74.29,53.59 74.9,52.99 75.65,52.99 76.04,53.38 76.04,53.76 v1(76.18,53.89)
RZ_CSI_DATA0_N: length 72
  TOP w0.13: v1(66.52,58.02) 66.69,57.85 66.69,56.52 U26.63 ; v1(15.03,54.4) 14.89,54.25 14.07,54.25 13.96,54.15 13.73,54.15 U6.C6
  ART03 w0.109: v1(15.03,54.4) 15.2,54.23 15.49,54.23 15.61,54.36 15.82,54.36 15.94,54.23 16.15,54.23 16.27,54.36 16.47,54.36 16.6,54.23 16.83,54.23 18.18,55.58 21.73,55.58 23.79,57.63 26.74,57.63 30.11,61.01 39.14,61.01 40.36,62.23 43.3,62.23 43.4,62.34 43.4,63.46 43.83,63.88 44.78,63.88 45.08,63.58 45.08,62.08 45.19,61.97 45.63,61.97 45.74,62.08 45.74,63.58 46.04,63.88 47.29,63.88 48.49,62.68 49.53,62.68 49.83,62.38 49.83,61.17 49.94,61.06 50.38,61.06 50.49,61.17 50.49,62.38 50.79,62.68 57.35,62.68 58.98,61.06 60.51,61.06 62.28,59.29 62.43,59.29 63.13,59.98 63.56,59.98 64.06,59.48 64.06,59.06 63.36,58.36 63.36,58.21 64.04,57.53 64.64,57.53 64.77,57.66 64.97,57.66 65.1,57.53 65.3,57.53 65.42,57.66 65.62,57.66 65.75,57.53 65.95,57.53 66.08,57.66 66.28,57.66 66.41,57.53 66.62,57.53 66.74,57.64 66.74,57.8 v1(66.52,58.02)
RZ_CSI_DATA0_P: length 72
  TOP w0.13: U6.C5 13.75,53.82 14.1,53.82 14.2,53.93 14.84,53.93 v1(15.03,53.74) ; U26.62 67.01,56.52 67.01,57.85 v1(67.18,58.02)
  ART03 w0.109: v1(15.03,53.74) 15.2,53.9 16.97,53.9 18.31,55.25 21.87,55.25 23.93,57.3 26.87,57.3 30.25,60.68 39.27,60.68 40.49,61.9 43.43,61.9 43.73,62.2 43.73,63.32 43.97,63.55 44.65,63.55 44.76,63.44 44.76,61.95 45.06,61.65 45.77,61.65 46.07,61.95 46.07,63.44 46.18,63.55 47.16,63.55 48.35,62.36 49.4,62.36 49.5,62.25 49.5,61.03 49.81,60.73 50.51,60.73 50.82,61.03 50.82,62.25 50.92,62.36 57.22,62.36 58.84,60.73 60.37,60.73 62.14,58.96 62.57,58.96 63.27,59.66 63.42,59.66 63.73,59.35 63.73,59.19 63.03,58.5 63.03,58.07 63.9,57.2 66.76,57.2 67.06,57.51 67.06,57.9 v1(67.18,58.02)
RZ_CSI_DATA1_N: length 72.1
  TOP w0.13: v1(14.41,53.47) 14.28,53.34 13.74,53.34 U6.C4 ; v1(69.52,57.78) 69.69,57.62 69.69,56.52 U26.60
  ART03 w0.109: v1(69.52,57.78) 69.69,57.61 69.69,56.71 69.34,56.36 68.99,56.36 68.87,56.49 68.67,56.49 68.54,56.36 68.34,56.36 68.21,56.49 68.01,56.49 67.88,56.36 67.38,56.36 67,56.74 63.57,56.74 60.14,60.17 57.44,60.17 57.33,60.28 57.33,61.32 57.03,61.62 56.32,61.62 56.02,61.32 56.02,60.28 55.91,60.17 55.48,60.17 55.37,60.28 55.37,61.32 55.07,61.62 54.36,61.62 54.06,61.32 54.06,60.28 53.95,60.17 53.51,60.17 53.4,60.28 53.4,61.32 53.1,61.62 52.39,61.62 52.09,61.32 52.09,60.28 51.98,60.17 48.54,60.17 47.77,60.93 40.73,60.93 39.94,60.15 30.9,60.15 27.17,56.41 24.2,56.41 22.3,54.51 20.11,54.51 18.9,53.31 17.81,53.31 17.7,53.42 17.48,53.42 17.37,53.31 17.15,53.31 17.04,53.42 16.82,53.42 16.71,53.31 16.5,53.31 16.38,53.42 16.17,53.42 16.06,53.31 15.84,53.31 15.73,53.42 15.51,53.42 15.4,53.31 14.58,53.31 v1(14.41,53.47)
RZ_CSI_DATA1_P: length 72.1
  TOP w0.13: v1(70.18,57.78) 70.01,57.61 70.01,56.52 U26.59 ; v1(14.41,52.81) 14.21,53.01 13.74,53.01 U6.C3
  ART03 w0.109: v1(14.41,52.81) 14.58,52.98 19.04,52.98 20.24,54.18 22.43,54.18 24.34,56.09 27.3,56.09 31.04,59.82 40.08,59.82 40.87,60.61 47.64,60.61 48.4,59.84 52.12,59.84 52.42,60.15 52.42,61.18 52.53,61.29 52.96,61.29 53.07,61.18 53.07,60.15 53.37,59.84 54.08,59.84 54.38,60.15 54.38,61.18 54.49,61.29 54.93,61.29 55.04,61.18 55.04,60.15 55.34,59.84 56.05,59.84 56.35,60.15 56.35,61.18 56.46,61.29 56.9,61.29 57.01,61.18 57.01,60.15 57.31,59.84 60.01,59.84 63.44,56.41 66.87,56.41 67.25,56.03 69.47,56.03 70.01,56.57 70.01,57.61 v1(70.18,57.78)
RZ_CSI_DATA2_N: length 72.1
  TOP w0.13: U5.C4 14.18,50.44 v1(14.34,50.6) ; v1(63.54,54.96) 63.66,55.08 63.66,55.87 U26.66
  ART03 w0.109: v1(63.54,54.96) 63.7,54.81 63.7,54.11 63.54,53.95 63,53.95 60.73,56.21 59.88,56.21 59.72,56.37 59.72,57.92 59.42,58.22 58.71,58.22 58.41,57.92 58.41,56.44 58.18,56.21 57.84,56.21 57.52,56.52 57.52,57.79 57.17,58.14 56.29,58.14 55.98,57.84 55.98,56.9 55.87,56.79 55.44,56.79 55.33,56.9 55.33,57.84 55.03,58.14 54.32,58.14 54.02,57.84 54.02,56.9 53.91,56.79 53.47,56.79 53.36,56.9 53.36,57.64 53.06,57.94 40.23,57.94 39.93,57.64 39.93,56.98 39.82,56.87 39.38,56.87 39.28,56.98 39.28,57.64 38.97,57.94 38.27,57.94 37.96,57.64 37.96,56.98 37.86,56.87 37.42,56.87 37.31,56.98 37.31,57.64 37.01,57.94 34.25,57.94 33.85,57.53 33.25,57.53 32.66,58.11 31.66,58.11 28.03,54.48 25.77,54.48 24.64,53.35 24.64,52.92 25.02,52.54 25.02,52.39 24.71,52.08 24.56,52.08 24.08,52.55 23.44,52.55 22.96,52.07 20.79,52.07 20.27,51.55 20.27,50.83 19.87,50.44 18.51,50.44 18.38,50.57 18.18,50.57 18.05,50.44 17.86,50.44 17.72,50.57 17.53,50.57 17.4,50.44 17.2,50.44 17.07,50.57 16.87,50.57 16.74,50.44 16.55,50.44 16.41,50.57 16.22,50.57 16.09,50.44 15.89,50.44 15.76,50.57 15.56,50.57 15.43,50.44 15.24,50.44 15.1,50.57 14.91,50.57 14.77,50.44 14.51,50.44 v1(14.34,50.6)
RZ_CSI_DATA2_P: length 72.1
  TOP w0.13: U5.C3 13.78,50.11 14.18,50.11 v1(14.34,49.94) ; U26.65 63.99,55.82 63.99,55.18 v1(64.2,54.96)
  ART03 w0.109: v1(14.34,49.94) 14.51,50.11 20.01,50.11 20.6,50.7 20.6,51.41 20.93,51.74 23.09,51.74 23.58,52.22 23.95,52.22 24.42,51.75 24.85,51.75 25.35,52.25 25.35,52.68 24.97,53.06 24.97,53.22 25.9,54.15 28.16,54.15 31.8,57.78 32.53,57.78 33.11,57.2 33.98,57.2 34.39,57.61 36.87,57.61 36.98,57.5 36.98,56.84 37.28,56.54 37.99,56.54 38.29,56.84 38.29,57.5 38.4,57.61 38.84,57.61 38.95,57.5 38.95,56.84 39.25,56.54 39.96,56.54 40.26,56.84 40.26,57.5 40.37,57.61 52.93,57.61 53.04,57.5 53.04,56.77 53.34,56.46 54.04,56.46 54.35,56.77 54.35,57.7 54.46,57.81 54.89,57.81 55,57.7 55,56.77 55.3,56.46 56.01,56.46 56.31,56.77 56.31,57.7 56.42,57.81 57.04,57.81 57.2,57.65 57.2,56.39 57.7,55.88 58.32,55.88 58.73,56.3 58.73,57.78 58.84,57.89 59.28,57.89 59.39,57.78 59.39,56.23 59.74,55.88 60.6,55.88 62.86,53.62 63.68,53.62 64.03,53.97 64.03,54.79 v1(64.2,54.96)
RZ_CSI_DATA3_N: length 72
  TOP w0.13: v1(72.49,54.49) 72.66,54.65 72.66,55.12 72.35,55.43 U26.57 ; v1(15.06,49.65) 14.89,49.48 13.99,49.48 13.83,49.64 U5.C2
  ART03 w0.109: v1(72.49,54.49) 72.66,54.32 72.66,53.29 72.45,53.08 71.05,53.08 70.94,53.19 70.94,53.62 70.64,53.92 69.93,53.92 69.63,53.62 69.63,53.19 69.52,53.08 69.08,53.08 68.97,53.19 68.97,53.62 68.67,53.92 67.96,53.92 67.66,53.62 67.66,53.19 67.55,53.08 67.11,53.08 67,53.19 67,53.62 66.7,53.92 65.99,53.92 65.69,53.62 65.69,53.19 65.58,53.08 62.56,53.08 60.78,54.86 58.85,54.86 58.44,55.27 57.43,55.27 56.71,55.98 52.63,55.98 51.58,57.02 41.57,57.02 40.58,56.03 36.6,56.03 35.86,56.77 34.34,56.77 33.63,56.06 31.59,56.06 28.9,53.37 27.4,53.37 24.98,50.95 23.08,50.95 21.43,49.3 20.98,49.3 20.8,49.48 18.63,49.48 18.5,49.61 18.3,49.61 18.18,49.48 17.98,49.48 17.85,49.61 17.65,49.61 17.52,49.48 17.32,49.48 17.19,49.61 16.99,49.61 16.87,49.48 16.67,49.48 16.54,49.61 16.34,49.61 16.21,49.48 16.01,49.48 15.88,49.61 15.68,49.61 15.56,49.48 15.23,49.48 v1(15.06,49.65)
RZ_CSI_DATA3_P: length 72.1
  TOP w0.13: U26.56 73.35,55.43 72.99,55.07 72.99,54.65 v1(73.15,54.49) ; U5.C1 13.79,49.15 14.89,49.15 v1(15.06,48.99)
  ART03 w0.109: v1(73.15,54.49) 72.99,54.32 72.99,53.15 72.59,52.76 70.91,52.76 70.61,53.06 70.61,53.49 70.5,53.6 70.06,53.6 69.95,53.49 69.95,53.06 69.65,52.76 68.94,52.76 68.64,53.06 68.64,53.49 68.53,53.6 68.1,53.6 67.99,53.49 67.99,53.06 67.69,52.76 66.98,52.76 66.68,53.06 66.68,53.49 66.57,53.6 66.13,53.6 66.02,53.49 66.02,53.06 65.72,52.76 62.42,52.76 60.64,54.54 58.71,54.54 58.31,54.94 57.29,54.94 56.58,55.65 52.49,55.65 51.45,56.7 41.71,56.7 40.71,55.7 36.46,55.7 35.73,56.44 34.47,56.44 33.76,55.73 31.73,55.73 29.04,53.04 27.53,53.04 25.12,50.62 23.21,50.62 21.56,48.97 20.84,48.97 20.66,49.15 15.23,49.15 v1(15.06,48.99)
RZ_DEBUGEN: length 34
  TOP w0.152: SW1.5 92.24,6.79 91.89,7.14 v1(91.89,7.62) ; U26.141 v1(63.35,12.6)
  ART03 w0.152: v1(63.35,12.6) 63.35,12.49 63.83,12.01 67.1,12.01 68.12,11 77.39,11 77.97,11.58 84.91,11.58 86.13,10.36 88.34,10.36 91.08,7.62 v1(91.89,7.62)
RZ_DISP_DATA0: length 70.1
  TOP w0.152: U26.L17 v1(82.09,51.92) ; U22.44 v1(30.3,53)
  ART04 w0.152: v1(48.59,66.14) 46.53,66.14 41.3,60.91 40.76,60.91 37.61,57.76 33.78,57.76 32.94,56.92 32.36,56.92 30.3,54.86 v1(30.3,53)
  BOTTOM w0.152: U22.44 v1(30.3,53) ; v1(82.09,51.92) 81.63,52.37 78.02,52.37 77.52,52.88 77.52,55.02 75.94,56.59 62.28,56.59 56.87,62 56.87,65.15 55.88,66.14 v1(48.59,66.14)
RZ_DISP_DATA1: length 72.1
  TOP w0.152: U22.38 31.01,47.6 v1(31.24,47.37) ; U26.L18 v1(79.55,51.92)
  ART04 w0.152: v1(31.24,47.37) 31.64,47.76 31.64,49.57 32.03,49.96 32.03,52.91 33.04,53.92 33.04,55.47 34.57,57 38.15,57 41.3,60.15 41.96,60.15 47.27,65.46 48.15,65.46 v1(48.43,65.18)
  BOTTOM w0.152: v1(79.55,51.92) 77.92,51.92 77.11,52.73 77.11,54.97 75.94,56.13 62.07,56.13 56.41,61.8 56.41,64.82 55.55,65.68 48.94,65.68 v1(48.43,65.18) ; R213.1 v1(31.24,47.37)
RZ_DISP_DATA3: length 1.6
  TOP w0.152: U26.L20 v1(74.47,51.92)
  BOTTOM w0.152: U26.L20 v1(74.47,51.92)
RZ_DISP_DATA4: length 67.1
  TOP w0.152: R217.2 29.18,41.56 29.74,41 v1(29.84,41) ; U26.L21 v1(71.93,51.92)
  ART04 w0.152: v1(29.84,41) 30.45,41.61 30.45,47.6 31.26,48.41 31.26,49.83 31.59,50.16 31.59,53.14 32.51,54.05 32.51,55.75 34.21,57.45 37.99,57.45 41.04,60.5 41.63,60.5 v1(46.58,65.46)
  BOTTOM w0.152: v1(71.93,51.92) 70.96,52.88 64.08,52.88 54.35,62.61 49.42,62.61 v1(46.58,65.46)
RZ_DISP_DATA6: length 52
  TOP w0.152: U26.L23 v1(66.85,51.92)
  ART04 w0.152: v1(33.12,48.18) 33.12,51.54 34.62,53.04 35.63,53.04 35.89,53.29 35.89,53.77 36.37,54.25 36.85,54.25 38.27,55.68 41.7,55.68 45.77,59.74 45.77,61.77 v1(46.73,62.74)
  BOTTOM w0.152: v1(33.12,48.18) 33.45,48.51 33.45,48.93 U23.1 32.25,48.96 R246.2 R242.1 ; v1(46.73,62.74) 47.24,62.23 54.12,62.23 63.8,52.55 66.21,52.55 v1(66.85,51.92)
RZ_DISP_DATA7: length 40.2
  TOP w0.152: U26.L24 v1(64.31,51.92)
  ART04 w0.152: v1(46.71,61.77) 47.14,61.34 47.14,59.41 42.95,55.22 42.95,53.87 43.15,53.67 43.15,50.37 42.38,49.6 v1(41.8,49.6)
  BOTTOM w0.152: v1(64.31,51.92) 63.78,51.92 53.92,61.77 v1(46.71,61.77) ; v1(41.8,49.6) R245.2 40.86,49.61 U23.15
RZ_DISP_DATA8: length 42.5
  TOP w0.152: U26.L25 v1(61.77,51.92) ; 33.42,53.51 32.49,53.51 R244.2 R241.1 ; 33.42,53.51 U24.1 ; 33.42,53.51 v1(34.76,53.51)
  ART04 w0.152: v1(34.76,53.51) 34.76,54.09 36.7,56.03 41.53,56.03 44.29,58.8 v1(44.29,61.34)
  BOTTOM w0.152: v1(61.77,51.92) 60.17,51.92 58.21,53.87 58.21,56.64 53.64,61.21 44.42,61.21 v1(44.29,61.34)
RZ_DISP_DATA9: length 35.6
  TOP w0.152: U24.15 39.22,52.86 40.79,52.86 R243.2 40.89,52.82 41.6,53.53 41.6,54.31 41.42,54.48 40.84,54.48 40.38,54.03 v1(39.11,54.03) ; U26.L26 v1(59.23,51.92)
  ART04 w0.152: v1(46.35,60.17) 46.15,59.97 46.15,59.36 42.06,55.27 41.47,55.27 40.28,54.08 39.16,54.08 v1(39.11,54.03)
  BOTTOM w0.152: v1(46.35,60.17) 46.68,60.5 53.72,60.5 57.81,56.41 57.81,53.82 59.23,52.4 v1(59.23,51.92)
RZ_DISP_DATA20: length 28
  TOP w0.152: U7.12 26.43,32.12 26.59,31.95 v1(27.22,31.95) ; U26.L38 48.99,32.49 v1(47.75,32.49)
  BOTTOM w0.152: v1(47.75,32.49) 47.39,32.13 47.39,29.67 46.66,28.93 32.91,28.93 30.15,31.7 27.48,31.7 v1(27.22,31.95)
RZ_DISP_DATA22: length 58.8
  TOP w0.152: U26.L40 48.08,28.32 v1(48.08,29.21) ; v1(27.2,40.26) 27.45,40.51 27.45,41.53 27.68,41.76 27.68,42.54 27.35,42.87 R215.1 27.01,43.32 26.74,43.59 25.24,43.59 24.51,44.32 23.57,44.32 23.41,44.48 23.41,46.41 23.16,46.66 22.58,46.66 22.12,47.12 22.12,51.31 21.54,51.89 20.49,51.89 17.59,54.8 U22.16
  ART04 w0.152: v1(27.2,40.26) 27.2,39.5 30.45,36.25 30.45,31.88 30.07,31.5 28.95,31.5 v1(28.06,30.61)
  BOTTOM w0.152: v1(28.06,30.61) 28.22,30.76 28.65,30.76 29.28,30.12 30.73,30.12 32.53,28.32 47.19,28.32 v1(48.08,29.21)
RZ_DISP_DATA23: length 65.3
  TOP w0.152: v1(29.16,59.03) 29.16,58.58 U22.50 29.9,58.4 30.9,59.41 R214.1 ; U26.L41 47.6,26.26 47.6,29.39 v1(48.08,29.87)
  ART04 w0.152: v1(28.98,40.79) 29.87,41.68 29.87,54.1 27.43,56.54 27.43,58.22 28.24,59.03 v1(29.16,59.03)
  BOTTOM w0.152: v1(48.08,29.87) 46.83,28.63 32.71,28.63 30.88,30.45 29.41,30.45 28.62,31.24 27.2,31.24 26.39,32.05 26.39,37.52 27.43,38.56 29.56,38.56 29.71,38.71 29.71,40.46 29.38,40.79 v1(28.98,40.79)
RZ_DSI_CLK_N: length 59.1
  TOP w0.13: v1(49.43,54.11) 49.58,54.25 49.58,54.51 49.43,54.66 49.02,54.66 48.68,54.99 48.68,55.55 48.35,55.89 U26.81 ; R95.2 28.78,24.76 29.11,24.76 v1(29.28,24.93)
  ART03 w0.109: v1(29.28,24.93) 29.44,24.76 29.61,24.76 29.74,24.89 29.93,24.89 30.06,24.76 30.7,24.76 30.87,24.94 30.87,25.11 31.02,25.26 31.19,25.26 31.34,25.4 31.34,25.58 31.48,25.72 31.66,25.72 32.44,26.51 32.99,26.51 33.09,26.62 33.09,27.05 32.99,27.16 32.35,27.16 32.05,27.46 32.05,28.24 32.35,28.54 34.33,28.54 34.52,28.72 34.52,29.01 34.33,29.19 32.35,29.19 32.05,29.49 32.05,30.2 32.35,30.5 34.33,30.5 34.44,30.61 34.44,31.05 34.33,31.16 32.35,31.16 32.05,31.46 32.05,34.81 33.22,35.97 33.22,39.24 40.91,46.94 42.51,46.94 42.8,47.23 42.8,48.33 43.1,48.64 43.76,48.64 43.86,48.74 43.86,49.18 43.76,49.29 43.1,49.29 42.8,49.59 42.8,51.92 43.4,52.53 44.47,52.53 46,54.05 47.27,54.05 47.65,53.67 48.04,53.67 48.17,53.8 48.37,53.8 48.5,53.67 48.7,53.67 48.83,53.8 49.03,53.8 49.15,53.67 49.49,53.67 49.6,53.78 49.6,53.93 v1(49.43,54.11)
RZ_DSI_CLK_P: length 59.1
  TOP w0.13: R93.2 28.78,24.44 29.11,24.44 v1(29.28,24.27) ; U26.80 49.35,55.88 49.01,55.54 49.01,55.13 49.15,54.99 49.56,54.99 49.91,54.64 49.91,54.36 50.09,54.18 v1(50.09,54.11)
  ART03 w0.109: v1(29.28,24.27) 29.44,24.44 30.83,24.44 32.58,26.18 33.12,26.18 33.42,26.48 33.42,27.19 33.12,27.49 32.49,27.49 32.38,27.6 32.38,28.1 32.49,28.21 34.47,28.21 34.84,28.59 34.84,29.14 34.47,29.52 32.49,29.52 32.38,29.63 32.38,30.07 32.49,30.18 34.47,30.18 34.77,30.48 34.77,31.19 34.47,31.49 32.49,31.49 32.38,31.6 32.38,34.67 33.55,35.84 33.55,39.11 41.05,46.61 42.64,46.61 43.13,47.09 43.13,48.2 43.23,48.31 43.89,48.31 44.19,48.61 44.19,49.32 43.89,49.62 43.23,49.62 43.13,49.73 43.13,51.78 43.54,52.2 44.61,52.2 46.13,53.72 47.14,53.72 47.52,53.34 49.63,53.34 49.93,53.64 49.93,53.94 v1(50.09,54.11)
RZ_DSI_DATA0_N: length 58.7
  TOP w0.13: R82.2 28.78,21.21 29.11,21.21 v1(29.28,21.37) ; v1(57.54,52.6) 57.71,52.77 57.71,55.07 57.35,55.43 U26.72
  ART03 w0.109: v1(57.54,52.6) 57.71,52.44 57.71,52.23 57.6,52.12 57.19,52.12 57.07,52.25 56.87,52.25 56.74,52.12 56.54,52.12 56.41,52.25 56.21,52.25 56.08,52.12 55.88,52.12 55.76,52.25 55.56,52.25 55.43,52.12 55.23,52.12 55.1,52.25 54.9,52.25 54.77,52.12 49.15,52.12 48.59,51.56 48.59,48.9 47.89,48.21 47.74,48.21 47.49,48.46 47.06,48.46 46.56,47.96 46.56,47.53 46.81,47.28 46.81,47.13 44.97,45.29 42.28,45.29 36.19,39.2 36.19,28 35.81,27.62 35.81,26.79 36.22,26.38 36.22,24.29 35.32,23.39 34.79,23.39 33.88,22.48 31.49,22.48 30.11,21.11 29.55,21.11 v1(29.28,21.37)
RZ_DSI_DATA0_P: length 58.8
  TOP w0.13: v1(58.2,52.6) 58.04,52.77 58.04,55.12 58.35,55.43 U26.71 ; R88.2 28.78,20.88 29.11,20.88 v1(29.28,20.71)
  ART03 w0.109: v1(58.2,52.6) 58.04,52.44 58.04,52.09 57.74,51.79 49.28,51.79 48.92,51.43 48.92,48.77 48.03,47.88 47.6,47.88 47.35,48.13 47.2,48.13 46.89,47.82 46.89,47.67 47.14,47.42 47.14,46.99 45.11,44.96 42.42,44.96 36.52,39.07 36.52,27.86 36.14,27.48 36.14,26.92 36.54,26.52 36.54,24.15 35.46,23.07 34.93,23.07 34.02,22.15 31.62,22.15 30.25,20.78 29.34,20.78 v1(29.28,20.71)
RZ_DSI_DATA1_N: length 59.2
  TOP w0.13: U26.75 54.35,55.43 54.68,55.09 54.68,53.79 v1(54.52,53.62) ; R90.2 28.78,22.99 29.11,22.99 v1(29.28,23.15)
  ART03 w0.109: v1(54.52,53.62) 54.68,53.45 54.68,53.22 54.42,52.96 54.14,52.96 54.01,53.09 53.81,53.09 53.68,52.96 53.48,52.96 53.35,53.09 53.15,53.09 53.03,52.96 52.83,52.96 52.7,53.09 52.5,53.09 52.37,52.96 52.17,52.96 52.04,53.09 51.84,53.09 51.72,52.96 51.52,52.96 51.39,53.09 51.19,53.09 51.06,52.96 48.04,52.96 47.29,52.2 45.98,52.2 45.44,51.66 45.44,50.27 45.74,49.97 46.04,49.97 46.15,49.86 46.15,49.42 46.04,49.31 45.74,49.31 45.44,49.01 45.44,47.05 44.46,46.07 41.52,46.07 34.14,38.69 34.14,35.7 32.97,34.53 32.97,32.36 33.34,31.98 34.99,31.98 35.48,31.49 35.48,28.56 33.98,27.06 33.98,26.03 34.35,25.66 34.92,25.66 35.03,25.55 35.03,24.93 34.82,24.72 32.8,24.72 31.75,23.67 30.83,23.67 30.15,22.99 29.44,22.99 v1(29.28,23.15)
RZ_DSI_DATA1_P: length 59.2
  TOP w0.13: U26.74 55.35,55.43 55.01,55.09 55.01,53.79 v1(55.18,53.62) ; R89.2 28.78,22.66 29.11,22.66 v1(29.28,22.49)
  ART03 w0.109: v1(55.18,53.62) 55.01,53.45 55.01,53.08 54.56,52.63 48.18,52.63 47.43,51.88 46.11,51.88 45.76,51.53 45.76,50.41 45.87,50.3 46.18,50.3 46.48,50 46.48,49.29 46.18,48.99 45.87,48.99 45.76,48.88 45.76,46.91 44.6,45.75 41.65,45.75 34.46,38.56 34.46,35.56 33.3,34.39 33.3,32.49 33.48,32.31 35.12,32.31 35.81,31.62 35.81,28.42 34.31,26.92 34.31,26.16 34.49,25.98 35.05,25.98 35.35,25.68 35.35,24.79 34.96,24.4 32.93,24.4 31.88,23.35 30.97,23.35 30.28,22.66 29.44,22.66 v1(29.28,22.49)
